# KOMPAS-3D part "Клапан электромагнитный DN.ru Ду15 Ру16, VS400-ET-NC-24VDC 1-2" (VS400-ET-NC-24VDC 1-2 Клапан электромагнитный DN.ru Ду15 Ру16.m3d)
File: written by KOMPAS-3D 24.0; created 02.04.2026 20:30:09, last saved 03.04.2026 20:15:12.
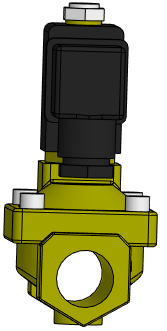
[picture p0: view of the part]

Document properties: Автор: artio; Полное имя файла: C:\Users\artio\OneDrive\Рабочий стол\Клапан электромагнитный DN.ru\VS400-ET-NC\VS400-ET-NC-24VDC 1-2 Клапан электромагнитный DN.ru Ду15 Ру16.m3d

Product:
- Body: Тело 1  | qty 1
    Масса: 1.030062
- Part/product: Клапан электромагнитный DN.ru Ду15 Ру16  | designation VS400-ET-NC-24VDC 1-2
    Масса: 0.759
    Раздел спецификации: Прочие изделия
    Примечание: D130-04719
    additional columns: ef56311e-7521-43dc-8291-0e6108b3d81d; VS400-ET-NC-220VAC 1-2; artio; c; Шероховатость не задана; Да

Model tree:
1. Операция без истории:1

Expressions: VS400-ET-NC-24VDC 1-2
